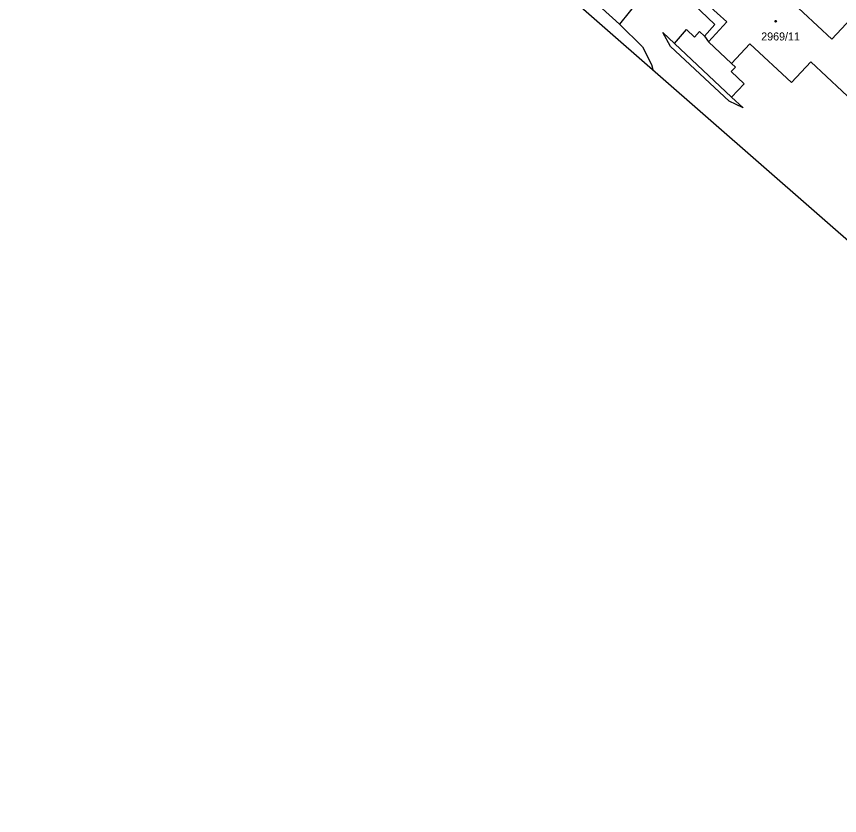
# Model space of a CAD drawing. Extents: x -620475 to -619963, y -1123010 to -1122510.
# Drawn here: x -620474.6 to -620299.9, y -1123010.1 to -1122840.5 of the extents above; entities that cross this region are included whole.
import ezdxf

# ---------------------------------------------------------------- set-up
doc = ezdxf.new("R2010")
doc.units = 0
for name, color, linetype in [('Hranice parcel', 7, 'Continuous'), ('Parcelní čísla', 7, 'Continuous'), ('Rámečky', 7, 'Continuous'), ('Rámečky-tisk', 7, 'Continuous'), ('Vnitřní kresba', 7, 'Continuous'), ('Značky budov', 7, 'Continuous')]:
    doc.layers.add(name, color=color, linetype=linetype)

msp = doc.modelspace()

# ---------------------------------------------------------------- linework, layer by layer
at = {"layer": 'Hranice parcel'}
for points in [[(-620326.76, -1122819.51), (-620336.22, -1122829.85), (-620337.65, -1122831.34), (-620340.44, -1122834.38), (-620346.62, -1122842.11), (-620352.46, -1122836.69), (-620354.47, -1122835.76), (-620356.61, -1122835.3), (-620358.07, -1122835.57)], [(-620319.79, -1122828.24), (-620301.53, -1122845.3), (-620297.45, -1122840.93)], [(-620282.72, -1122871.91), (-620306.02, -1122850.12), (-620310.12, -1122854.5), (-620318.93, -1122846.25), (-620322.84, -1122850.43), (-620322, -1122851.22), (-620322.9, -1122852.18), (-620320.12, -1122854.78), (-620322.8, -1122857.63), (-620334.93, -1122846.23), (-620332.41, -1122843.27), (-620330.68, -1122844.83), (-620329.65, -1122843.69), (-620328.57, -1122844.67), (-620327.72, -1122845.89), (-620323.82, -1122841.64), (-620329.96, -1122836)]]:
    msp.add_lwpolyline(points, dxfattribs=at)
at = {"layer": 'Rámečky'}
msp.add_lwpolyline([(-620279.07, -1122510.07), (-620474.61, -1122733.62), (-620158.49, -1123010.14)], dxfattribs=at)
at = {"layer": 'Rámečky-tisk'}
msp.add_lwpolyline([(-620279.07, -1122510.07), (-620474.61, -1122733.62), (-620158.49, -1123010.14)], dxfattribs=at)
at = {"layer": 'Vnitřní kresba'}
for p, q in [((-620337.65, -1122831.34), (-620326.36, -1122842.19)), ((-620346.62, -1122842.11), (-620341.73, -1122846.95)), ((-620326.36, -1122842.19), (-620328.57, -1122844.67)), ((-620337.39, -1122843.9), (-620334.93, -1122846.23)), ((-620335.79, -1122846.87), (-620337.39, -1122843.9)), ((-620327.72, -1122845.89), (-620322.84, -1122850.43)), ((-620341.73, -1122846.95), (-620339.83, -1122850.67)), ((-620323.32, -1122858.48), (-620335.79, -1122846.87)), ((-620339.83, -1122850.67), (-620339.56, -1122851.76)), ((-620320.33, -1122859.87), (-620323.32, -1122858.48)), ((-620322.8, -1122857.63), (-620320.33, -1122859.87))]:
    msp.add_line(p, q, dxfattribs=at)
at = {"layer": 'Značky budov'}
msp.add_circle((-620313.46, -1122841.47), 0.175, dxfattribs=at)

# ---------------------------------------------------------------- texts
at = {"layer": 'Parcelní čísla'}
msp.add_text('2969/11', height=1.7, dxfattribs=at).set_placement((-620316.52, -1122845.56))

doc.saveas('drawing.dxf')
